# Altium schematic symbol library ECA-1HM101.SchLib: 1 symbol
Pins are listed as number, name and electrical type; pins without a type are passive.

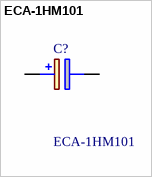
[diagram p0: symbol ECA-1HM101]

## ECA-1HM101
designator C?
Aluminum Electrolytic Capacitors - Leaded 100uF 50V; Manufacturer_Name: Panasonic; Geometry.Height: 12.5mm
footprint CAPPRD350W65D825H1250
pins: 1 +, 2 -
